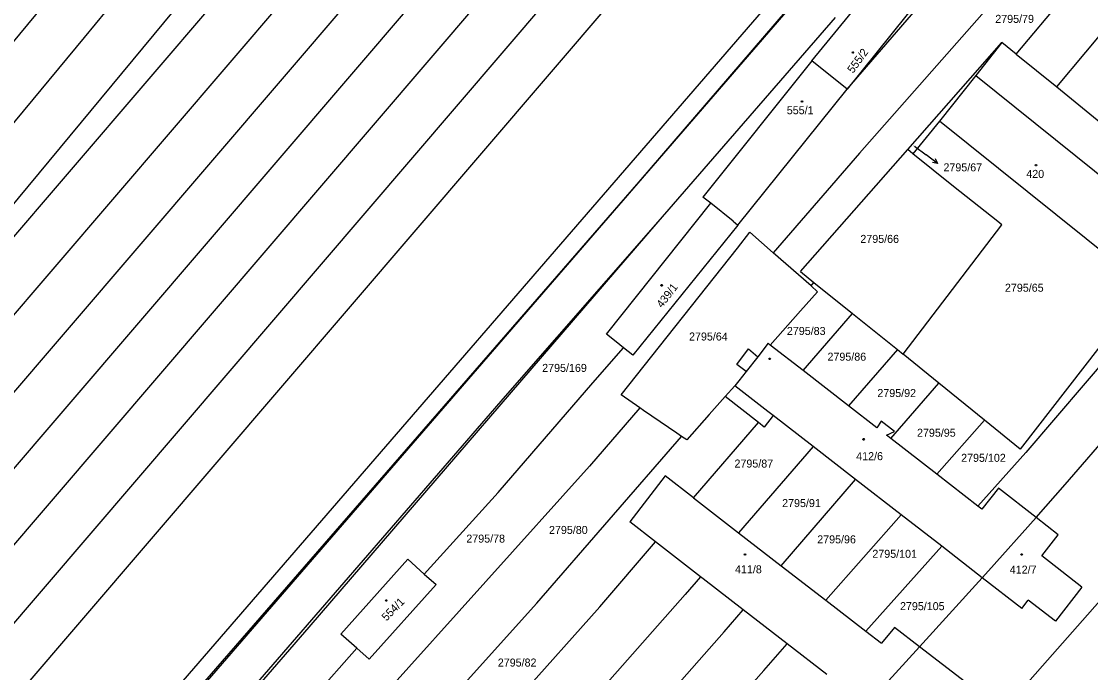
# Model space of a CAD drawing. Extents: x -580630 to -576196, y -1189024 to -1183567.
# Drawn here: x -579205 to -578977.9, y -1186072.7 to -1185934.4 of the extents above; entities that cross this region are included whole.
import ezdxf

# ---------------------------------------------------------------- set-up
doc = ezdxf.new("R2010")
doc.units = 0
for name, color, linetype in [('Vrstva 1', 7, 'Continuous'), ('Vrstva 16', 7, 'Continuous'), ('Vrstva 18', 7, 'Continuous'), ('Vrstva 19', 7, 'Continuous'), ('Vrstva 25', 7, 'Continuous'), ('Vrstva 4', 7, 'Continuous'), ('Vrstva 6', 7, 'Continuous'), ('Vrstva 63', 7, 'Continuous')]:
    doc.layers.add(name, color=color, linetype=linetype)

msp = doc.modelspace()

# ---------------------------------------------------------------- linework, layer by layer
at = {"layer": 'Vrstva 1'}
for p, q in [((-579043.07, -1185789.08), (-579516.28, -1186341.47)), ((-579560.3, -1186409.54), (-579034.2, -1185795.41)), ((-579025.51, -1185801.62), (-579550.65, -1186414.64)), ((-579541.04, -1186419.71), (-579016.85, -1185807.81)), ((-579008.27, -1185813.94), (-579531.52, -1186424.74)), ((-578999.43, -1185820.25), (-579414.73, -1186305.04)), ((-579236.45, -1186009.08), (-579080.09, -1185820.33)), ((-579398.1, -1186301.88), (-578990.93, -1185826.58)), ((-578979.05, -1185852.8), (-579170.73, -1186074.45)), ((-579167.73, -1186077.09), (-578979.81, -1185859.79)), ((-579037.07, -1185942.75), (-579019.92, -1185921.72)), ((-579012.69, -1185927.7), (-579029.6, -1185948.76)), ((-579032.1, -1185933.51), (-579069.79, -1185976.93)), ((-579016.71, -1185961.59), (-578996.72, -1185938.83)), ((-578996.72, -1185938.83), (-579002.21, -1185945.89)), ((-578993.65, -1185941.32), (-578996.72, -1185938.83)), ((-579037.07, -1185942.75), (-579060.21, -1185971.67)), ((-579029.6, -1185948.76), (-579037.07, -1185942.75)), ((-578993.65, -1185941.32), (-578985.03, -1185948.3)), ((-579002.21, -1185945.89), (-579009.99, -1185955.55)), ((-579002.21, -1185945.89), (-578962.78, -1185977.56)), ((-579052.83, -1185977.62), (-579029.6, -1185948.76)), ((-578985.03, -1185948.3), (-578975.67, -1185955.88)), ((-579009.99, -1185955.55), (-579015.62, -1185962.52)), ((-578970.53, -1185987.21), (-579009.99, -1185955.55)), ((-579039.48, -1185987.52), (-579016.71, -1185961.59)), ((-579015.62, -1185962.52), (-579016.71, -1185961.59)), ((-579006.97, -1185969.42), (-579015.62, -1185962.52)), ((-578997.6, -1185976.88), (-579006.97, -1185969.42)), ((-579058.57, -1185972.99), (-579060.21, -1185971.67)), ((-579080.68, -1186000.79), (-579058.57, -1185972.99)), ((-579053.83, -1185976.81), (-579058.57, -1185972.99)), ((-579069.79, -1185976.93), (-579143.98, -1186063.03)), ((-579069.79, -1185976.93), (-579102.25, -1186013.96)), ((-579053.83, -1185976.81), (-579052.83, -1185977.62)), ((-578996.72, -1185977.58), (-578997.6, -1185976.88)), ((-578949.68, -1185976.92), (-578991.64, -1186025.94)), ((-579052.83, -1185977.62), (-579075.11, -1186005.29)), ((-579052.9, -1185982.53), (-579050.27, -1185979.17)), ((-579045.27, -1185983.55), (-579050.27, -1185979.17)), ((-579017.71, -1186005.03), (-578996.72, -1185977.58)), ((-578958.51, -1185980.85), (-578992.81, -1186025.26)), ((-579077.6, -1186013.72), (-579052.9, -1185982.53)), ((-579037.25, -1185990.57), (-579045.27, -1185983.55)), ((-579039.48, -1185987.52), (-579036.64, -1185989.81)), ((-579035.89, -1185991.78), (-579037.25, -1185990.57)), ((-579036.64, -1185989.81), (-579028.47, -1185996.38)), ((-579035.89, -1185991.78), (-579039.5, -1185995.86)), ((-579039.5, -1185995.86), (-579045.91, -1186003.16)), ((-579028.47, -1185996.38), (-579018.91, -1186004.07)), ((-579078.66, -1186002.42), (-579080.68, -1186000.79)), ((-579077.11, -1186003.68), (-579078.66, -1186002.42)), ((-579075.11, -1186005.29), (-579077.11, -1186003.68)), ((-579053.03, -1186007.22), (-579050.51, -1186003.94)), ((-579050.51, -1186003.94), (-579048.58, -1186005.59)), ((-579046.35, -1186002.71), (-579048.58, -1186005.59)), ((-579045.91, -1186003.16), (-579046.35, -1186002.71)), ((-579038.94, -1186008.55), (-579045.91, -1186003.16)), ((-579018.91, -1186004.07), (-579017.71, -1186005.03)), ((-579010.08, -1186011.23), (-579017.71, -1186005.03)), ((-579051.03, -1186008.73), (-579053.03, -1186007.22)), ((-579051.03, -1186008.73), (-579052.58, -1186010.71)), ((-579029.28, -1186016.03), (-579038.94, -1186008.55)), ((-579052.58, -1186010.71), (-579053.46, -1186011.75)), ((-579000.41, -1186019.08), (-579010.08, -1186011.23)), ((-579073.62, -1186016.44), (-579077.6, -1186013.72)), ((-579055.51, -1186014.06), (-579053.46, -1186011.75)), ((-579102.25, -1186013.96), (-579162.21, -1186083.17)), ((-579058.88, -1186017.86), (-579055.51, -1186014.06)), ((-579048.44, -1186019.58), (-579055.51, -1186014.06)), ((-579023.28, -1186020.67), (-579029.28, -1186016.03)), ((-579072.82, -1186016.99), (-579073.62, -1186016.44)), ((-579065.78, -1186021.81), (-579072.82, -1186016.99)), ((-579058.88, -1186017.86), (-579063.65, -1186023.27)), ((-579045.32, -1186018.07), (-579047.21, -1186020.54)), ((-579036.79, -1186024.69), (-579045.32, -1186018.07)), ((-579047.21, -1186020.54), (-579048.44, -1186019.58)), ((-579022.34, -1186019.27), (-579023.28, -1186020.67)), ((-579019.55, -1186021.49), (-579022.34, -1186019.27)), ((-578992.81, -1186025.26), (-579000.41, -1186019.08)), ((-579064.76, -1186022.51), (-579065.78, -1186021.81)), ((-579063.65, -1186023.27), (-579064.76, -1186022.51)), ((-579021.19, -1186022.29), (-579019.55, -1186021.49)), ((-579020.27, -1186023), (-579021.19, -1186022.29)), ((-579027.78, -1186031.68), (-579036.79, -1186024.69)), ((-579010.53, -1186030.56), (-579020.27, -1186023)), ((-579068.27, -1186030.92), (-579075.76, -1186040.7)), ((-579062.22, -1186035.6), (-579068.27, -1186030.92)), ((-579018.13, -1186039.17), (-579027.78, -1186031.68)), ((-579001.83, -1186037.31), (-579010.53, -1186030.56)), ((-578997.4, -1186033.55), (-579000.94, -1186038)), ((-578989.46, -1186039.74), (-578997.4, -1186033.55)), ((-579062.22, -1186035.6), (-579052.66, -1186042.98)), ((-579000.94, -1186038), (-579001.83, -1186037.31)), ((-579070.27, -1186044.95), (-579075.76, -1186040.7)), ((-579009.5, -1186045.87), (-579018.13, -1186039.17)), ((-578984.72, -1186043.43), (-578989.46, -1186039.74)), ((-579052.66, -1186042.98), (-579043.6, -1186049.98)), ((-579060.76, -1186052.32), (-579070.27, -1186044.95)), ((-578988.22, -1186047.92), (-578984.72, -1186043.43)), ((-579000.87, -1186052.56), (-579009.5, -1186045.87)), ((-579137.15, -1186064.53), (-579122.94, -1186048.61)), ((-579122.94, -1186048.61), (-579119.45, -1186051.78)), ((-579043.6, -1186049.98), (-579034.12, -1186057.3)), ((-578979.71, -1186054.55), (-578988.22, -1186047.92)), ((-579119.45, -1186051.78), (-579116.93, -1186053.97)), ((-579060.19, -1186052.76), (-579060.76, -1186052.32)), ((-579116.93, -1186053.97), (-579131.14, -1186069.82)), ((-579051.7, -1186059.34), (-579060.19, -1186052.76)), ((-578992.44, -1186059.1), (-579000.87, -1186052.56)), ((-578979.71, -1186054.55), (-578985.34, -1186061.78)), ((-579034.12, -1186057.3), (-579025.63, -1186063.86)), ((-578992.44, -1186059.1), (-578991.1, -1186057.31)), ((-578985.34, -1186061.78), (-578991.1, -1186057.31)), ((-579042.32, -1186066.61), (-579051.7, -1186059.34)), ((-579143.98, -1186063.03), (-579180.14, -1186104.89)), ((-579019.54, -1186063.11), (-579022.28, -1186066.45)), ((-579014.22, -1186067.2), (-579019.54, -1186063.11)), ((-579133.74, -1186067.53), (-579137.15, -1186064.53)), ((-579025.63, -1186063.86), (-579022.28, -1186066.45)), ((-579131.14, -1186069.82), (-579133.74, -1186067.53)), ((-579033.92, -1186073.12), (-579042.32, -1186066.61)), ((-579004.47, -1186074.69), (-579014.22, -1186067.2))]:
    msp.add_line(p, q, dxfattribs=at)
at = {"layer": 'Vrstva 16'}
for p in [(-579015.29, -1185960.89), (-579010.364, -1185964.518)]:
    msp.add_line(p, (-579012.78, -1185962.74), dxfattribs=at)
msp.add_lwpolyline([(-579010.873, -1185963.523), (-579010.364, -1185964.518), (-579011.465, -1185964.328)], dxfattribs=at)
at = {"layer": 'Vrstva 25'}
for points in [[(-579028.28, -1185940.84), (-579028.19, -1185940.99), (-579028.28, -1185941.14), (-579028.46, -1185941.14), (-579028.55, -1185940.99), (-579028.46, -1185940.84)], [(-579039.09, -1185951.24), (-579039, -1185951.39), (-579039.09, -1185951.54), (-579039.27, -1185951.54), (-579039.36, -1185951.39), (-579039.27, -1185951.24)], [(-578989.38, -1185964.76), (-578989.29, -1185964.91), (-578989.38, -1185965.06), (-578989.56, -1185965.06), (-578989.65, -1185964.91), (-578989.56, -1185964.76)], [(-579068.91, -1185990.28), (-579068.82, -1185990.43), (-579068.91, -1185990.58), (-579069.09, -1185990.58), (-579069.18, -1185990.43), (-579069.09, -1185990.28)], [(-579045.97, -1186005.92), (-579045.88, -1186006.07), (-579045.97, -1186006.22), (-579046.15, -1186006.22), (-579046.24, -1186006.07), (-579046.15, -1186005.92)], [(-579026.01, -1186023), (-579025.92, -1186023.15), (-579026.01, -1186023.3), (-579026.19, -1186023.3), (-579026.28, -1186023.15), (-579026.19, -1186023)], [(-579051.2, -1186047.44), (-579051.11, -1186047.59), (-579051.2, -1186047.74), (-579051.38, -1186047.74), (-579051.47, -1186047.59), (-579051.38, -1186047.44)], [(-578992.42, -1186047.44), (-578992.33, -1186047.59), (-578992.42, -1186047.74), (-578992.6, -1186047.74), (-578992.69, -1186047.59), (-578992.6, -1186047.44)], [(-579127.42, -1186057.23), (-579127.33, -1186057.38), (-579127.42, -1186057.53), (-579127.6, -1186057.53), (-579127.69, -1186057.38), (-579127.6, -1186057.23)]]:
    msp.add_lwpolyline(points, close=True, dxfattribs=at)
at = {"layer": 'Vrstva 4'}
for p, q in [((-579048.58, -1186005.59), (-579051.03, -1186008.73)), ((-579046.41, -1186017.22), (-579053.46, -1186011.75)), ((-579045.32, -1186018.07), (-579046.41, -1186017.22))]:
    msp.add_line(p, q, dxfattribs=at)
at = {"layer": 'Vrstva 6'}
for p, q in [((-579256.06, -1185998.51), (-579064.92, -1185766.8)), ((-579100.1, -1185826.68), (-579191.69, -1185937.77)), ((-579029.6, -1185948.76), (-578957.26, -1185865.31)), ((-578993.65, -1185941.32), (-578939.33, -1185876.42)), ((-578985.03, -1185948.3), (-578930.81, -1185882.98)), ((-578988.52, -1185918.71), (-579026.98, -1185962.34)), ((-578983.24, -1186032.73), (-578884.68, -1185918.52)), ((-579191.69, -1185937.77), (-579242.84, -1185999.49)), ((-579026.98, -1185962.34), (-579045.27, -1185983.55)), ((-579037.25, -1185990.57), (-579036.64, -1185989.81)), ((-579038.94, -1186008.55), (-579028.47, -1185996.38)), ((-579083.59, -1186011.15), (-579077.11, -1186003.68)), ((-579018.91, -1186004.07), (-579029.28, -1186016.03)), ((-579103.7, -1186034.45), (-579083.59, -1186011.15)), ((-579020.27, -1186023), (-579010.08, -1186011.23)), ((-579073.62, -1186016.44), (-579084.29, -1186028.83)), ((-579062.22, -1186035.6), (-579048.44, -1186019.58)), ((-579010.53, -1186030.56), (-579000.41, -1186019.08)), ((-579095.52, -1186057.95), (-579064.76, -1186022.51)), ((-579036.79, -1186024.69), (-579052.66, -1186042.98)), ((-578991.64, -1186025.94), (-579001.83, -1186037.31)), ((-579084.29, -1186028.83), (-579139.06, -1186089.72)), ((-579043.6, -1186049.98), (-579027.78, -1186031.68)), ((-578989.46, -1186039.74), (-578983.24, -1186032.73)), ((-579119.45, -1186051.78), (-579103.7, -1186034.45)), ((-579034.12, -1186057.3), (-579018.13, -1186039.17)), ((-578999.52, -1186051.08), (-578989.46, -1186039.74)), ((-579082.14, -1186058.74), (-579070.27, -1186044.95)), ((-579009.5, -1186045.87), (-579025.63, -1186063.86)), ((-579005.3, -1186090.77), (-578966.94, -1186047.25)), ((-579060.76, -1186052.32), (-579064.02, -1186056.07)), ((-579000.87, -1186052.56), (-578999.52, -1186051.08)), ((-579014.22, -1186067.2), (-579000.87, -1186052.56)), ((-579064.02, -1186056.07), (-579101.92, -1186098.99)), ((-579146.71, -1186130.91), (-579082.14, -1186058.74)), ((-579138.83, -1186105.95), (-579095.52, -1186057.95)), ((-579055.73, -1186064), (-579051.7, -1186059.34)), ((-579092.73, -1186106.04), (-579055.73, -1186064)), ((-579146.22, -1186081.56), (-579133.74, -1186067.53)), ((-579047.31, -1186072.27), (-579042.32, -1186066.61)), ((-579023.71, -1186077.61), (-579014.22, -1186067.2)), ((-579083.52, -1186113.11), (-579047.31, -1186072.27))]:
    msp.add_line(p, q, dxfattribs=at)
at = {"layer": 'Vrstva 63'}
for p, q in [((-579073.77, -1185968.44), (-579023.767, -1185910.263)), ((-579185.15, -1186096.56), (-579073.77, -1185968.44))]:
    msp.add_line(p, q, dxfattribs=at)

# ---------------------------------------------------------------- texts
at = {"layer": 'Vrstva 16'}
msp.add_text('2795/67', height=1.7, dxfattribs=at).set_placement((-579009.123, -1185966.22))
at = {"layer": 'Vrstva 18'}
for s, height, p in [('2795/79', 1.7, (-578998.112, -1185934.68)), ('2795/67', 0.1, (-579015.575, -1185960.89)), ('2795/66', 1.7, (-579026.782, -1185981.42)), ('2795/65', 1.7, (-578996.059, -1185991.79)), ('2795/83', 1.7, (-579042.386, -1186000.97)), ('2795/64', 1.7, (-579063.172, -1186002.15)), ('2795/86', 1.7, (-579033.759, -1186006.44)), ('2795/169', 1.7, (-579094.373, -1186008.82)), ('2795/92', 1.7, (-579023.166, -1186014.16)), ('2795/95', 1.7, (-579014.739, -1186022.59)), ('2795/87', 1.7, (-579053.519, -1186029.14)), ('2795/102', 1.7, (-579005.364, -1186027.92)), ('2795/91', 1.7, (-579043.394, -1186037.53)), ('2795/78', 1.7, (-579110.492, -1186045.08)), ('2795/80', 1.7, (-579092.926, -1186043.24)), ('2795/96', 1.7, (-579035.942, -1186045.24)), ('2795/101', 1.7, (-579024.232, -1186048.31)), ('2795/105', 1.7, (-579018.357, -1186059.43)), ('2795/82', 1.7, (-579103.803, -1186071.41))]:
    msp.add_text(s, height=height, dxfattribs=at).set_placement(p)
at = {"layer": 'Vrstva 19'}
for s, rotation, p in [('555/2', 53.97263, (-579028.335, -1185945.52)), ('439/1', 52.48293, (-579068.912, -1185995.356)), ('554/1', 45.37826, (-579127.463, -1186061.863))]:
    msp.add_text(s, height=1.7, rotation=rotation, dxfattribs=at).set_placement(p)
for s, p in [('555/1', (-579042.406, -1185954.09)), ('420', (-578991.525, -1185967.61)), ('412/6', (-579027.659, -1186027.57)), ('411/8', (-579053.407, -1186051.6)), ('412/7', (-578995.039, -1186051.67))]:
    msp.add_text(s, height=1.7, dxfattribs=at).set_placement(p)

doc.saveas('drawing.dxf')
